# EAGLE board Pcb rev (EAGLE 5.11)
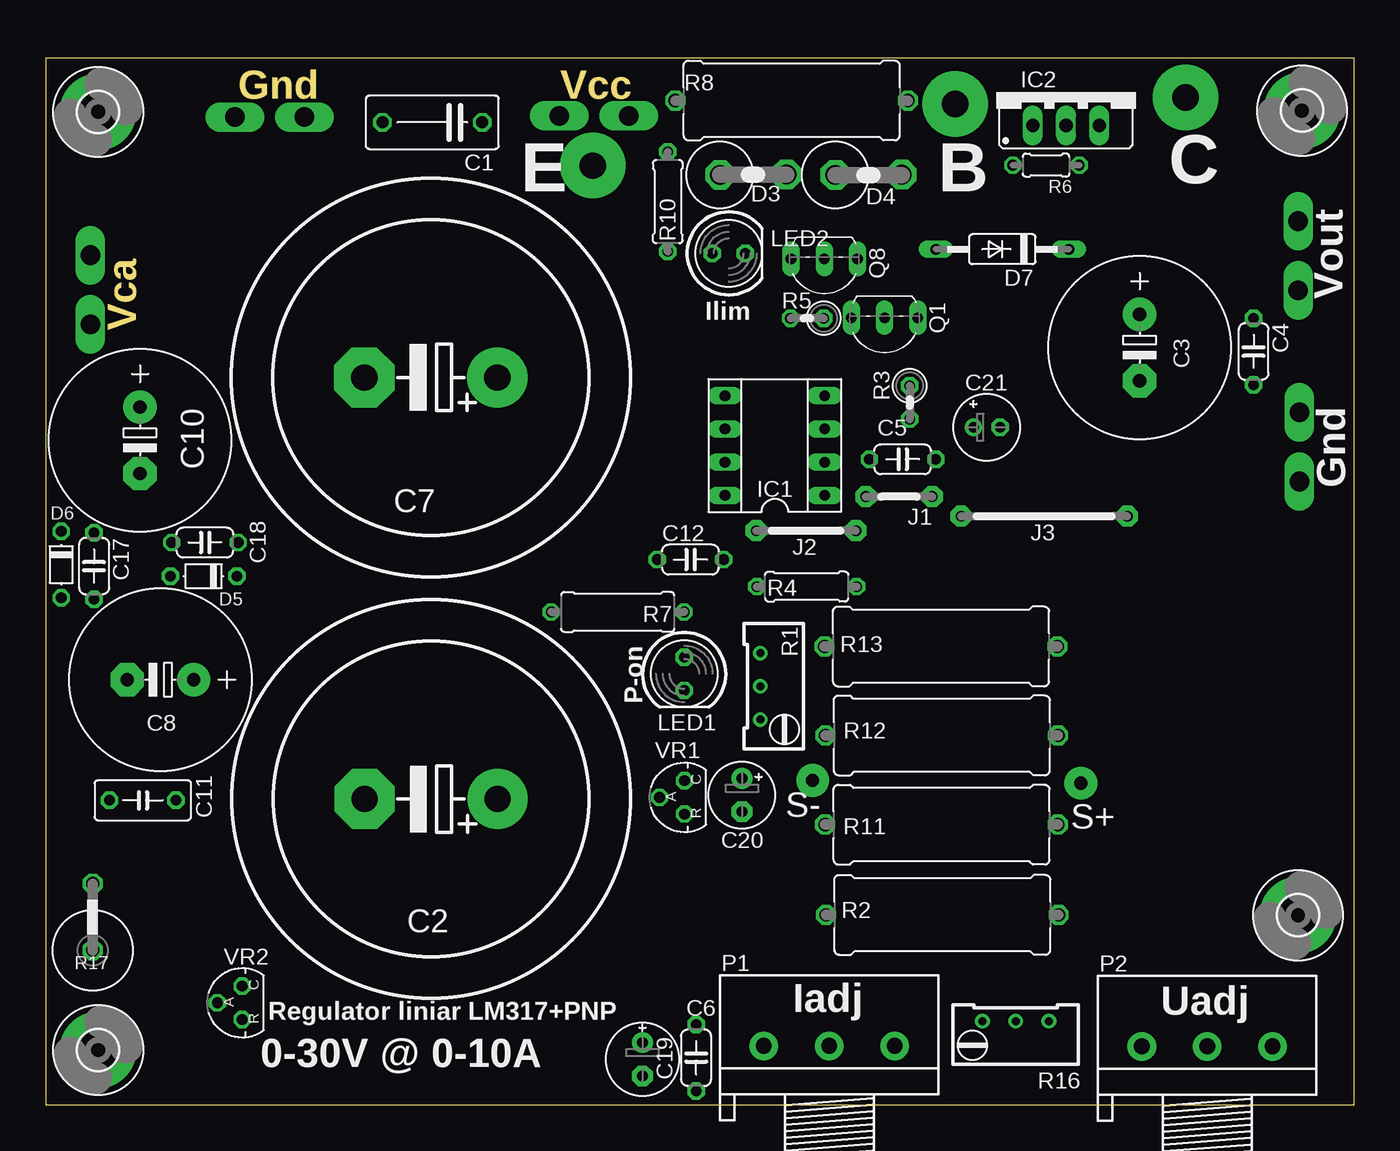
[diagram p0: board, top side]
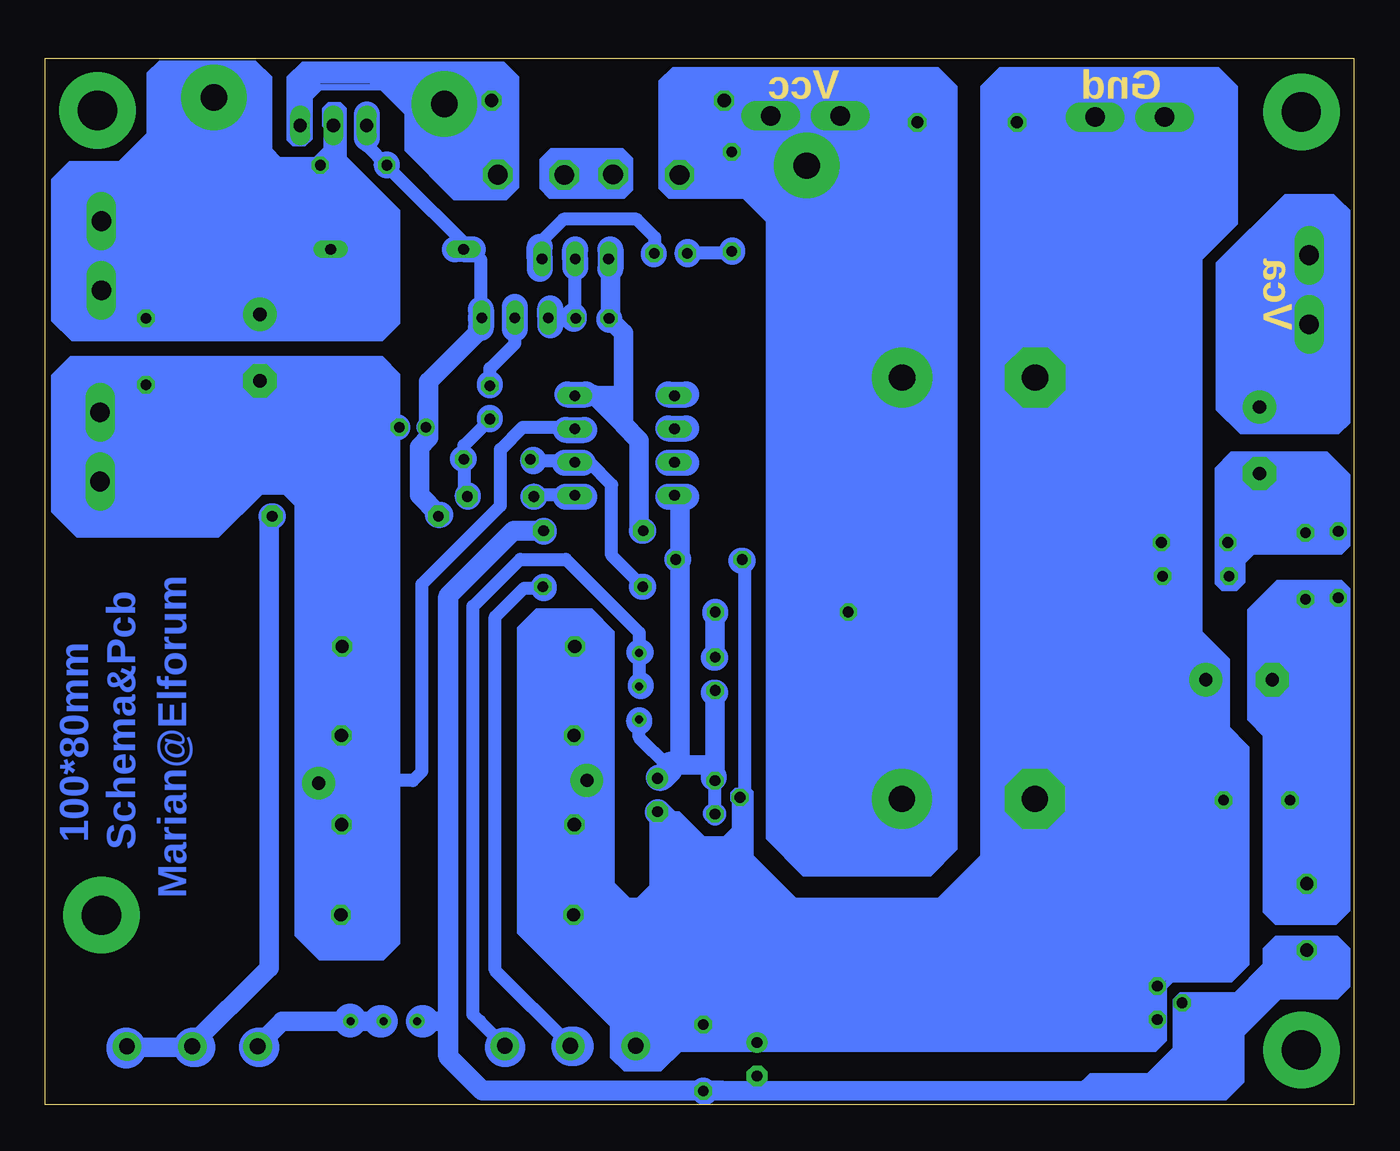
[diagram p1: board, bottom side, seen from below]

Size 100 x 80 mm. Coordinates in mm from the lower left corner, seen from the top.
Outline: 0,0 100,0 100,80 0,80 0,0
Copper layers (1*16): Top 0.035mm / dielectric 1.5mm / Bottom 0.035mm
Design rules "default": minimum track width 10mil, minimum drill 24mil, track to track 8mil, track to pad 8mil, pad to pad 8mil, via to via 8mil, smd to smd 8mil, copper to edge 40mil, drill to drill 8mil, minimum pad ring 10mil, minimum via ring 8mil, stop-mask expansion 4mil, vias tented up to drill 0mil, thermal gap 10mil

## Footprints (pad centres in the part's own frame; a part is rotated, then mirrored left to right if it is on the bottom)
C075-042X103 = drill 0.914 octagon: 1 -3.81,0; 2 3.81,0
EB30D = drill 2.007 pad 4.597 round: + -5.08,0 | drill 2.007 pad 4.597 octagon: - 5.08,0
E5-13 = drill 1.016 pad 2.54 round: + -2.54,0 | drill 1.016 pad 2.54 octagon: - 2.54,0
C050-024X044 = drill 0.813 octagon: 1 -2.54,0; 2 2.54,0
C050-030X075 = drill 0.813 octagon: 1 -2.54,0; 2 2.54,0
E2,5-6E = drill 0.813 pad 1.575 round: + -1.27,0 | drill 0.813 pad 1.575 octagon: - 1.27,0
E2,5-5 = drill 0.813 pad 1.6 round: + -1.27,0 | drill 0.813 pad 1.6 octagon: - 1.27,0
E2-5 = drill 0.813 pad 1.27 round: + -1.016,0 | drill 0.813 pad 1.27 octagon: - 1.016,0
RAD5G = drill 1.499 octagon: A 2.54,0.025; C -2.54,0
D-5 = drill 0.813 octagon: A 2.54,0; C -2.54,0
C2992 = drill 0.813 long: A 5.08,0; C -5.08,0
3,0-PAD = drill 3 pad 5.842 round: B3,0 0,0
62409-1 = drill 1.5 pad 1.9 long: A1 -2.65,0; A2 2.65,0
SOCKET-08 = drill 0.813 long: 1 -3.81,-3.81; 2 -1.27,-3.81; 3 1.27,-3.81; 4 3.81,-3.81; 5 3.81,3.81; 6 1.27,3.81; 7 -1.27,3.81; 8 -3.81,3.81
317TS = drill 1.016 long: 1 -2.54,-2.54; 2 0,-2.54; 3 2.54,-2.54
05 = drill 0.813 pad 1.6 octagon: 1 -2.54,0; 2 2.54,0
07 = drill 0.813 pad 1.6 octagon: 1 -3.81,0; 2 3.81,0
12 = drill 0.813 pad 1.6 octagon: 1 -6.35,0; 2 6.35,0
LED5MM = drill 0.813 octagon: A -1.27,0; K 1.27,0
3RP/1610N = drill 1.2 pad 2.184 round: 1 -5,0; 2 0,0; 3 5,0
TO92-EBC = drill 0.813 long: B 0,-1.27; C -2.54,-1.27; E 2.54,-1.27
RTRIM64W = drill 0.61 round: 1 1.27,-2.54; 2 1.27,0; 3 1.27,2.54
0617/17 = drill 1.016 octagon: 1 -8.89,0; 2 8.89,0
0207/2V = drill 0.813 octagon: 1 -1.27,0; 2 1.27,0
0207/7 = drill 0.813 octagon: 1 -3.81,0; 2 3.81,0
0204/5 = drill 0.813 octagon: 1 -2.54,0; 2 2.54,0
0309/10 = drill 0.813 octagon: 1 -5.08,0; 2 5.08,0
0617V = drill 1.016 octagon: 1 -2.54,0; 2 2.54,0
TO92-CLP = drill 0.813 octagon: A 0,1.905; C 1.27,0; R -1.27,0

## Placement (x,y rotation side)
C1  100n  [C075-042X103]  29.54,75.1 180 top
C2  10m  [EB30D]  29.44,23.39 180 top
C3  680u  [E5-13]  83.59,57.88 270 top
C4  100n  [C050-024X044]  92.3,57.59 270 top
C5  10n  [C050-024X044]  65.48,49.35 0 top
C6  1u  [C050-024X044]  49.7,3.61 90 top
C7  10m  [EB30D]  29.42,55.6 180 top
C8  470u  [E5-13]  8.76,32.5 180 top
C10  470u  [E5-13]  7.2,50.8 270 top
C11  100n  [C050-030X075]  7.41,23.29 0 top
C12  1u  [C050-024X044]  49.26,41.69 0 top
C17  1n  [C050-024X044]  3.69,41.19 270 top
C18  1n  [C050-024X044]  12.16,42.99 0 top
C19  1u  [E2,5-6E]  45.6,3.49 270 top
C20  1u  [E2,5-5]  53.2,23.69 270 top
C21  1u  [E2-5]  71.91,51.8 0 top
D3  UF5408  [RAD5G]  54.06,71.09 0 top
D4  UF5408  [RAD5G]  62.88,71.08 0 top
D5  UF4007  [D-5]  12.06,40.42 180 top
D6  UF4007  [D-5]  1.18,41.3 270 top
D7  [C2992]  73.1,65.4 180 top
E$1  [3,0-PAD]  4,75.9 0 top
E$2  [3,0-PAD]  4,4.2 0 top
E$3  [3,0-PAD]  95.7,14.5 0 top
E$4  [3,0-PAD]  96,76 0 top
E$5  [62409-1]  41.9,75.6 180 top
E$6  [62409-1]  17.1,75.5 0 top
E$7  [62409-1]  95.7,64.9 90 top
E$8  [62409-1]  95.8,50.3 90 top
E$9  [62409-1]  3.4,62.3 90 top
IC1  LM393  [SOCKET-08]  55.72,50.4 90 top
IC2  LM317HVT  [317TS]  77.97,77.41 0 top
J1  [05]  65.2,46.5 180 top
J2  [07]  58.1,43.9 0 top
J3  [12]  76.3,45 0 top
LED1  Verde  [LED5MM]  48.79,32.95 270 top
LED2  Rosu  [LED5MM]  52.19,65.09 0 top
P1  10k  [3RP/1610N]  59.87,4.52 0 top
P2  10k  [3RP/1610N]  88.76,4.48 0 top
Q1  BC547C  [TO92-EBC]  64.1,58.9 180 top
Q8  BC547C  [TO92-EBC]  59.49,63.4 180 top
R1  [RTRIM64W]  55.88,32 180 top
R2  100m/5W  [0617/17]  68.51,14.53 0 top
R3  27k  [0207/2V]  66.02,53.69 270 top
R4  10k  [0207/7]  58.15,39.62 0 top
R5  10k  [0207/2V]  58.18,60.13 180 top
R6  430  [0204/5]  76.44,71.83 180 top
R7  4k7/0,5W  [0309/10]  43.7,37.68 180 top
R8  10  [0617/17]  57,76.77 0 top
R10  6k8  [0207/7]  47.53,69.04 90 top
R11  100m/5W  [0617/17]  68.45,21.43 0 top
R12  100m/5W  [0617/17]  68.47,28.25 0 top
R13  100m/5W  [0617/17]  68.41,35.05 0 top
R16  1k  [RTRIM64W]  74.12,5.14 90 top
R17  2k7/0,5W  [0617V]  3.58,14.37 90 top
VR1  TL431  [TO92-CLP]  48.81,23.51 90 top
VR2  TL431  [TO92-CLP]  15.01,7.81 90 top

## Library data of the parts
C1-C8 C10-C12 C17-C21 R1 R3-R8 R10 R16 R17 = resistor
D3-D7 = diode
E$1-E$4 = holes
E$5-E$9 = con-faston
IC1 = ic-package
IC2 = v-reg
J1-J3 = jumper
LED1 LED2 = led
P1 P2 = pot
Q1 Q8 = transistor-npn
R2 R11-R13 = resistor; OC_FARNELL: unknown; OC_NEWARK: unknown
VR1 VR2 = v-reg2

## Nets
N$30: LED1.K
V-: IC1.4

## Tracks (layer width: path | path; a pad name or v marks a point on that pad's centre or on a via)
S$1
  Bottom 2: 54.3,39.6 54.4,39.6
S$2
  Bottom 0.5: 66.8,6.4 67.4,7
  Bottom 1: 54.6,32 54.6,34.6 54.6,36.1 60.2,41.7 63.7,41.7 67.3,38.1 67.3,6.9 66.8,6.4 64.9,4.5
  Bottom 2: 54.6,34.6 54.5,34.6
S$3
  Bottom 0.5: 54.5,29.4 54.5,28.1 52.2,25.8
S$4
  Bottom 0.5: 32.4,17.7 30.5,19.6 30.5,77.8 31.8,79.1 52,79.1 52.9,78.2 52.9,70.1 52.3,69.5 46.6,69.5 44.7,67.6 44.7,20.4 42,17.7 32.4,17.7
S$5
  Bottom 0.5: 48.7,34.4 48.8,37.6
  Bottom 2: 48.8,37.7 48.8,37.6
S$6
  Bottom 1: 61.8,43.7 64.1,43.7 68.9,38.9 68.9,3.8 66.1,1 50,1 49.9,1.1
  Bottom 1.5: 49.7,1.1 49.9,1.1 | 19.9,1.1 48.3,1.1
  Bottom 1.52: 48.3,1.1 49.7,1.1 66.6,1.1 69.2,3.7 69.2,38.9 64.2,43.9 62,43.9
  Bottom 2: 49.6,1 49.7,1.1
S$7
  Bottom 1: 77.3,24.8 71.9,24.8 71.2,25.5 71.2,39.8 65.2,45.8 65.2,50.1 63.5,51.8 59.2,51.8
S$8
  Bottom 1: 59.9,4.6 65.6,10.3 65.6,37.3 63.4,39.5 62,39.5
S$9
  Bottom 1: 54.3,39.5 54.3,39.6 56.7,42 56.7,47.4 58.4,49.1 59.6,49.1
S$10
  Bottom 2: 61.9,39.5 61.9,39.6
S$11
  Bottom 1: 59.5,49.2 62.6,49.2
S$12
  Bottom 1: 77.3,14.4 77.3,35.1 | 77.3,14.4 77.4,14.3 | 77.3,14.4 77.2,14.5
S$13
  Bottom 0.5: 19.6,75.8 20.4,75
S$14
  Bottom 0.5: 5.9,14 6.7,14.8 6.7,28.3 7.9,29.5 7.9,37.8 5.8,39.9 1,39.9 0.5,39.4 0.5,14.9 1.4,14 5.9,14
S$15
  Bottom 0.5: 39.1,75.7 38.3,74.9
S$16
  Bottom 0.5: 1.2,69 1.6,69.4 5.2,69.4 10.3,64.3 10.3,53.2 8.6,51.5 1.2,51.5 0.5,52.2 0.5,68.3 1.2,69
S$17
  Bottom 0.5: 48.8,25.4 48.8,22.3 | 48.8,25.9 51.6,25.9 | 51.6,25.9 52.2,25.9 | 51.6,25.9 51.6,38 51.6,39.1
  Bottom 1: 52.2,25.9 51.6,26.5 51.6,38 51.6,41.7 51.6,46.2 52,46.6 | 48.8,25.9 48.8,31.5 48.8,31.6 48.8,31.7 | 48.8,22.2 48.8,25.4 48.8,25.9 | 48.8,25.9 52.2,25.9 | 52.2,25.9 52.3,25.9
  Bottom 1.5: 48.8,31.6 48.8,25.4
  Bottom 2: 48.9,31.5 48.8,31.5 | 52.2,25.9 52.2,26 | 51.7,41.7 51.6,41.7
S$18
  Bottom 0.5: 15.7,2.2 13.6,4.3 13.6,8 13.2,8.4 9,8.4 6.7,10.7 6.7,11.9 5.9,12.7 1.3,12.7 0.5,11.9 0.5,9.1 1.3,8.3 5.7,8.3 8.6,5.4 8.6,1.8 9.8,0.6 21,0.6 21,1.3 20.1,2.2 15.7,2.2
S$19
  Bottom 0.5: 73.1,12.4 74.2,11.3 79,11.3 80.7,13 80.7,45.9 81.7,46.9 83.5,46.9 86.8,43.6 97.5,43.6 99.3,45.4 99.3,55.7 98,57 74.3,57 73.1,55.8 73.1,51.8 73.1,12.4
  Bottom 2: 73.2,51.8 73.1,51.8
S$20
  Bottom 0.5: 9.3,49.7 10.4,48.6 10.4,39.9 10,39.5 9,39.5 8.5,40 8.5,41.5 7.7,42.3 1,42.3 0.5,42.8 0.5,48.1 2.1,49.7 9.3,49.7
S$21
  Bottom 2: 61.9,43.9 61.9,43.8
S$22
  Bottom 1.5: 54.6,44.2 54.3,43.9
  Bottom 2: 54.3,43.9 54.4,43.9
S$23
  Bottom 2: 62.6,46.5 62.7,46.5
S$24
  Bottom 3: 93.8,4.3 93.8,4.4
S$25
  Bottom 1.5: 59.9,54.3 58.7,54.3 58.1,54.3 58,54.2 | 55.8,52 54.6,50.8 54.6,44.3 54.3,44 | 55.8,52 58,54.2 | 55.8,52 55.8,59 56.8,60 | 56.8,60 56.9,60.1 | 58,54.2 56,54.2 | 56.8,60 56.8,63.9 56.8,64.6
  Bottom 2: 56.8,65.4 56.8,63.9 | 56.9,60.1 56.9,60 | 60.1,54.3 58.7,54.3 | 60.2,51.6 58.8,51.6 | 60.3,49.1 58.9,49.1 | 60.2,46.5 58.8,46.5 | 52.4,46.5 51,46.5 | 52.4,49.1 51,49.1 | 52.4,51.7 51,51.7 | 52.4,54.3 51,54.3
S$26
  Bottom 1: 59.3,46.6 62.7,46.6
S$27
  Bottom 1: 54.6,29.3 54.6,28.1 52.4,25.9
  Bottom 2: 54.6,29.3 54.6,29.4
S$28
  Bottom 1: 59.5,60.1 59.6,60.1 61.6,60.1 | 59.5,60.1 59.4,60.1 | 59.5,60.1 59.5,64 | 59.5,64.6 59.5,64.7
  Bottom 2: 59.5,65.4 59.5,64.6 59.5,64 | 59.6,60.1 59.6,60.3
S$29
  Bottom 0.5: 48.8,34.2 48.8,34.3 48.8,37.2
  Bottom 1: 48.9,34.2 48.9,37.5
  Bottom 1.5: 48.8,37.5 48.8,34.3 48.9,34.2
  Bottom 2: 48.9,34.2 48.8,34.2
S$30  (via drill 1 pad 2.5)
  other vias: 79.1,24.6
S$31  (via drill 1 pad 2.5)
  other vias: 58.6,24.8
S$32
  Bottom 1.5: 70.8,51.8 70.9,51.8
S$33
  Bottom 1: 67.6,46.5 68,46.9 68,49.4 68,50.4 66,52.4
  Bottom 2: 68,49.4 68.1,49.4 | 66,52.4 66,52.5
S$34
  Bottom 2: 67.7,46.5 67.7,46.6
S$35
  Bottom 1: 66,55.1 66,56.3 64.1,58.2 64.1,59.3 | 64.1,59.4 64.1,60.1
  Bottom 2: 64.1,59.3 64.1,59.4 64.1,61 | 66,55 66,55.1
S$36
  Bottom 1: 47.5,65.1 50.9,65.1
S$37
  Bottom 1: 53.4,65 53.4,66.3 54.8,67.7 60.4,67.7 62,66.1 62,64.2
S$38
  Bottom 0.5: 55.3,70 55.8,69.5 61.4,69.5 62,70.1 62,72.2 61.3,72.9 55.9,72.9 55.3,72.3 55.3,70
S$39
  Bottom 1.5: 8.9,60.1 9.3,60.1 9.5,60.3 9.5,64 4.9,68.6 1.9,68.6 1.3,68 1.3,52.6 1.6,52.3 8.2,52.3 9.4,53.5 9.4,64.2 8.6,65
S$40
  Bottom 0.5: 80.9,75.6 79.9,75.6 79.9,77.3 79.2,78
S$41  (via drill 2 pad 5)
  other vias: 41.8,71.8
S$42  (via drill 2 pad 5)
  other vias: 87.1,77
S$43  (via drill 2 pad 5)
  other vias: 69.5,76.5
S$44
  Bottom 0.5: 79.8,74.9 80.5,74.9 | 79.8,74.9 79.8,76.1 | 79.8,76.1 79.8,77 79,77.8 72.8,77.8 | 79.8,76.1 80.3,76.1 | 79.8,74.9 79.8,73.9 80.2,73.5 81,73.5 81.3,73.8 81.3,78.5 80.3,79.5 72.6,79.5 | 72.8,79.2 72.8,79.3 72.6,79.5 | 72.6,79.5 71.7,79.5 65,79.5 64,78.5 64,70.2 64.8,69.4 68.7,69.4 72.3,73 72.3,75.8 75.1,78.6
  Bottom 1.5: 80.5,74.8 80.5,74.9 80.5,77.8 79.5,78.8 70.8,78.8
S$45
  Bottom 0.5: 80.7,58.6 97.9,58.6 99.3,60 99.3,70.7 98.1,71.9 94.3,71.9 92,74.2 92,78.8 91.2,79.6 84,79.6 82.9,78.5 82.9,73 82.1,72.2 78.9,72.2
S$46
  Bottom 2: 68.7,65.4 67.9,65.4 67.3,65.4
S$47
  Bottom 0.5: 80.1,79.3 80.1,79.2 81,78.3
S$48
  Bottom 1.5: 74.1,6.4 74.3,6.4 | 74.4,6.4 76.7,6.4 81.9,6.4 83.8,4.5
  Bottom 2.5: 76.7,6.4 76.7,6.5 | 74.3,6.4 74.4,6.4
S$49
  Bottom 1.5: 69.5,6.4 71.1,6.4 | 71.2,6.4 71.5,6.4
  Bottom 2.5: 71.2,6.4 71.1,6.4
S$50
  Bottom 1.5: 93.6,4.4 89,4.4 82.9,10.5 82.9,44.8 82.7,45 82.6,45.1
  Bottom 2: 82.7,45 82.6,45
S$52
  Bottom 1: 75.4,73.9 75.4,73.3 73.9,71.8 66.7,64.6 66.7,60.8 | 66.7,60.1 66.6,60.2
  Bottom 1.5: 66.7,60.2 66.7,59.3 70.7,55.3 70.7,51 71.4,50.3 71.4,46.6 70,45.2
  Bottom 2: 75.4,73.9 75.4,75.7 | 73.9,71.8 73.9,71.9 | 66.7,59.4 66.7,60.1 66.7,60.2 66.7,60.8
S$53
  Bottom 0.5: 78,74.9 78.6,74.9 78.6,76.1 78.3,76.4 77.5,76.4 77.2,76.1 77.2,72.4 73.1,68.3 73.1,59.8 74.3,58.6 82.4,58.6
  Bottom 1.5: 79.6,71.3 78,72.9 78,74.9
S$54
  Bottom 3: 6.3,59.2 6.3,55 7.3,54 7.3,63.6 4.3,66.6 3.4,66.6 3,67 3,53.7 2.7,53.4 5.5,53.4 5.5,63.6 4,65.1 4,54 4.5,53.5
S$55
  Bottom 1.5: 9.5,48.3 9,48.8 2.4,48.8 1.3,47.7 | 9.5,48.3 9.6,48.2 | 9.5,48.3 9.5,40.4 9.6,40.3 9.3,40.3 9.2,40.4 9.2,42 8.1,43.1 1.4,43.1 1.2,43.3 1.2,47.7 2.4,48.9 8.6,48.9 9.3,48.2 9.3,44.2 8.7,43.6 2.5,43.6 2,44.1 2,47.3 2.6,47.9 8.9,47.9 9,47.8 9,44.6 2.7,44.6 2.6,44.7 2.6,45.5 8.6,45.5 8.7,45.4 8.7,46.7 8.9,46.9 3.5,46.9 3.2,46.6
S$56
  Bottom 1.5: 3.9,15.5 1.2,15.5 1.1,15.6 1.1,38.9 1.3,39.1 5.5,39.1 7.1,37.5 7.1,29.7 5.9,28.5 5.9,15 5.7,14.8 2.8,14.8 2.2,15.4 2.2,38.1 4.8,38.1 5.8,37.1 5.8,30.1 4.8,29.1 4.8,15.8 2.5,15.8 2.4,15.7 2.4,16.9 4.4,16.9 4.6,16.7 4.6,17.8 4.7,17.9 3.7,17.9 3.6,18 3.6,36.8 3.4,37 4.3,37 4.6,36.7 4.6,29.8 4.1,29.3 3.8,29.3 3.5,29 3.5,26.3 3.1,25.9
S$57
  Bottom 1.5: 5.9,15.1 5.6,14.8 1.8,14.8 1.3,15.3
S$58
  Bottom 3: 4.3,16.7 4.3,16.4 3.3,16.4 3.2,16.5
S$59
  Bottom 1.5: 5.8,9.9 5.8,10.4 6,10.6 6,11.4 5.6,11.8 1.5,11.8 1.3,11.6 1.3,9.5 1.8,9 6.1,9 9.2,5.9 9.2,2.3 10.1,1.4 15.2,1.4 | 19.9,1.4 15.2,1.4 | 15.2,1.4 12.8,3.8 12.8,7.6 12.7,7.7 8.6,7.7 6.4,9.9 6,9.9 5.7,10.2
S$60
  Bottom 3: 5.2,10.8 2,10.8 2,10.2 2.1,10.1 5.3,10.1 5.4,10
S$61
  Bottom 2.54: 6,9.8 9.5,6.3
S$62
  Bottom 3: 11.3,6.6 11.3,4.2 13.5,2 11.7,2 10.3,3.4
S$63
  Bottom 1.5: 61.4,32.2 61.4,32.3 62.9,33.8 62.9,36 62.1,36.8 58.6,36.8 57.6,35.8 57.6,16.6 55.8,14.8 54.2,14.8 52.8,16.2 52.8,21.1 52.6,21.3 51.8,21.3 50,19.5 47.7,19.5 46.7,20.5 46.7,23.4
S$64
  Bottom 1.5: 47,19.9 47,18.7 43.1,14.8 31.3,14.8 27.3,18.8 27.3,19.1 27.5,19.3 27.5,77.5 26.8,78.2 10.8,78.2 9.9,77.3 9.9,67.8 12.4,65.3 12.4,28 9.1,24.7 9.1,11.2 9.8,10.5 14.4,10.5 15.3,9.6 15.3,5.4 15.7,5 52.1,5 53.5,3.6 55.5,3.6 55.8,3.9 55.8,6.5 62.8,13.5 62.8,34.6 62.7,34.7
S$65
  Bottom 3: 61.1,31 61.1,35.2 61.4,35.5 60,35.5 59.5,35 59.5,16.4 55.9,12.8 54.1,12.8 51.2,15.7 51.2,19.1 51.8,19.7 51.8,18.9 50.6,17.7 48.7,17.7 48.5,17.9 48.5,17.6 44.2,13.3 30.4,13.3 25.7,18 25.7,76.5 25.8,76.6 12.2,76.6 11.7,76.1 11.7,68.6 14.2,66.1 14.2,27 10.9,23.7 10.9,12.3 11,12.2 15.5,12.2 16.7,11 16.7,6.6 52.5,6.6 54.1,5 54.1,7.4 61.1,14.4 61.1,35.7 60.9,35.9
S$66
  Bottom 6.452: 55.5,10.9 53.5,10.9 50.1,14.3 50.1,13.8 47.7,11.4 47.7,11 48.8,9.9 52.9,9.9 53,10 28.3,10 22.7,15.6 22.7,73 22.4,73.3 15.9,73.3 15.2,74 15.2,70.7 17.5,68.4 17.5,24.8 14.9,22.2 14.9,15.5 15.3,15.1 17.6,15.1 19.2,13.5 19.2,10 20,9.2 23.5,9.2 23.9,8.8 23.9,12.7 18.8,17.8 18.8,22.4 19.6,23.2 19.6,14.9 17.7,13
S$67
  Bottom 1.5: 43.9,22.5 43.9,20.7 41.8,18.6 32.7,18.6 31.3,20 31.3,77.4 32.2,78.3 51.6,78.3 52.2,77.7 52.2,70.5 51.8,70.1 46.1,70.1 44.1,68.1 44.1,21.1 43,20
S$68
  Bottom 3: 42.8,23.3 42.8,21.5 41.6,20.3 33.5,20.3 33.2,20.6 33.2,76.1 33,76.3 49.9,76.3 50.3,76.7 50.3,72.3 50.7,71.9 45.7,71.9 42.4,68.6 42.4,21.3 40.7,19.6
S$69
  Bottom 6.452: 38.9,30.7 38.9,23.2 39.2,22.9 36.3,22.9 36.3,73.6 36,73.9 47.2,73.9 47.4,74.1 42.3,74.1 40.5,72.3 40.5,23.6 39.6,22.7
S$70
  Bottom 1.5: 58.5,71.1 58.5,70.2 61,70.2 61.2,70.4 61.2,72 61.1,72.1 56.2,72.1 56.1,72 56.1,70.4 56.3,70.2 60.7,70.2 61.3,70.8 56.8,70.8
S$71
  Bottom 1.5: 74.6,78.5 73.8,78.5 71.6,76.3 71.6,73.4 68.3,70.1 65.3,70.1 64.9,70.5 64.9,78.1 65.4,78.6 73.3,78.6 73.4,78.7 72.4,78.7 70.6,76.9
S$72
  Bottom 3: 70.6,77.7 70.6,74.7 67.3,71.4 66.2,71.4 66.2,77.3 65.8,77.7 67.9,77.7 68.2,78 68.2,74.3 68.1,74.2
S$73
  Bottom 1.5: 82.3,71 82.3,71.3 82.1,71.5 78.2,71.5 77.9,71.8 77.7,71.8 74,68.1 74,60 74.7,59.3 97.5,59.3 98.5,60.3 98.5,70.4 97.9,71 94,71 91.3,73.7 91.3,78.3 90.8,78.8 84.3,78.8 83.7,78.2 83.7,72.5 82.2,71
S$74
  Bottom 3: 89.2,68.9 79.6,68.9 78.3,70.2 78.3,69.8 75.8,67.3 75.8,60.9 75.7,60.8 96.7,60.8 97.1,61.2 97.1,69.4 96.9,69.6 92.9,69.6 89.9,72.6 89.9,77 89.6,77.3 85.4,77.3 85.3,77.2 85.3,71.7 84,70.4 78.6,70.4 78,69.8
S$75
  Bottom 6.452: 87.6,75.5 87.6,71.3 83.1,66.8 79.2,66.8 79.2,64.2 78.9,63.9 94.4,63.9 94.5,63.8 94.5,67 94.4,67.1 87.7,67.1 87.3,67.5 87.3,69.6 87.4,69.7 88.1,69.7 90.4,67.4
S$76
  Bottom 1.5: 98.4,49.2 98.4,49.5 | 98.4,49.5 98.4,55.4 97.6,56.2 74.6,56.2 73.8,55.4 73.8,13 74.6,12.2 78.6,12.2 79.9,13.5 79.9,46.2 81.4,47.7 83.9,47.7 87.2,44.4 97.3,44.4 98.5,45.6 98.5,49.4 98.4,49.5
S$77
  Bottom 3: 96.4,46.4 96.4,54.6 96.5,54.7 75.5,54.7 75.3,54.5 75.3,14.4 76.2,13.5 77.8,13.5 78.2,13.9 78.2,46.9 81.2,49.9 84.7,49.9 88.5,46.1 94.9,46.1 95.1,46.3 95.1,52.4 94.9,52.6 77.6,52.6 77.2,52.2 77.2,47.6 76.9,47.3 76.9,48.2 79.1,50.4 93.6,50.4 93.6,47.7 87.9,47.7 87.3,48.3 93.1,48.3 93.5,48.7
S$78
  Bottom 2: 61.4,60.9 61.4,60.2 61.4,59.6
S$79
  Bottom 2: 62.2,63.9 62.2,64.7 62.2,65.6
S$80
  Bottom 2: 53.5,65.1 53.5,65
S$81
  Bottom 2: 50.9,65 50.9,65.2
S$82
  Bottom 2: 47.5,65.3 47.5,65.2
S$84
  Bottom 0.5: 11.8,36.1 11.8,35 11.8,28.6 8.2,25 | 14.5,9 14.5,9.2 | 8.2,25 8.2,10.8 9.4,9.6 13.9,9.6 14.5,9 | 14.5,9 14.5,5 15.2,4.3 51.5,4.3 53,2.8 55.7,2.8 56.6,3.7 56.6,6.1 63.7,13.2 63.7,36.4 62.4,37.7 58.3,37.7 56.7,36.1 56.7,16.9 55.4,15.6 54.7,15.6 53.6,16.7 53.6,21.6 53,22.2 51.6,22.2 49.7,20.3 48.1,20.3 47.3,21.1 47.3,23.2 47.4,23.3 47.4,23.8 47.2,24 46.2,24 46.1,23.9 46.1,19 42.7,15.6 31.7,15.6 28.3,19 28.3,77.8 27,79.1 10.4,79.1 9.1,77.8 9.1,67.4 11.8,64.7 11.8,36.1 | 11.8,36.1 9.7,34 9.7,28.8 8.2,27.3 8.2,25
  Bottom 1.5: 9.1,25.2 9.1,27 10.4,28.3 10.4,33.6 11.8,35 11.8,28.7 11.1,28 11.1,33.4 12,34.3
S$85
  Bottom 2: 62.7,49.2 62.7,49.3
S$86
  Bottom 3: 7.7,46.8 7.8,46.9 3.1,46.9 2.8,46.6
S$87
  Bottom 2: 70,45.1 69.8,45.1
S$88
  Bottom 2: 54.5,32.1 54.5,32
S$89
  Bottom 2: 48.9,25 48.9,25.1
S$90
  Bottom 1.5: 49,22.3 48.7,22.3 48.7,22.2 48.8,22.1
S$91
  Bottom 3: 88.7,4.4 88.5,4.4
S$92
  Bottom 3: 83.7,4.4 83.6,4.4
S$93
  Bottom 3: 64.8,4.4 64.9,4.4
S$94
  Bottom 3: 59.8,4.5 59.6,4.5
S$95
  Bottom 1.5: 51.5,46.6 51.5,26.5 52.3,25.7
S$96
  Bottom 1.5: 51.5,26 49.1,26 49,26.1
S$97
  Bottom 1: 46.5,23.8 46.5,41.5
S$98
  Bottom 2: 46.8,41.6 46.7,41.6
S$99
  Bottom 2: 53.2,22.4 52.7,21.9
S$100
  Bottom 2: 53.1,25 52.9,25 52.3,25.6
S$102
  Bottom 3: 5.2,15.7 5.1,15.8

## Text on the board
Bottom: Marian@Elforum | Schema&Pcb | 100*80mm
Dimension: Gnd | Vcc | Vca
tNames: E | B | C | Vout | Ilim | Gnd | P-on | S- | S+ | Iadj | Uadj | Regulator liniar LM317+PNP | 0-30V @ 0-10A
